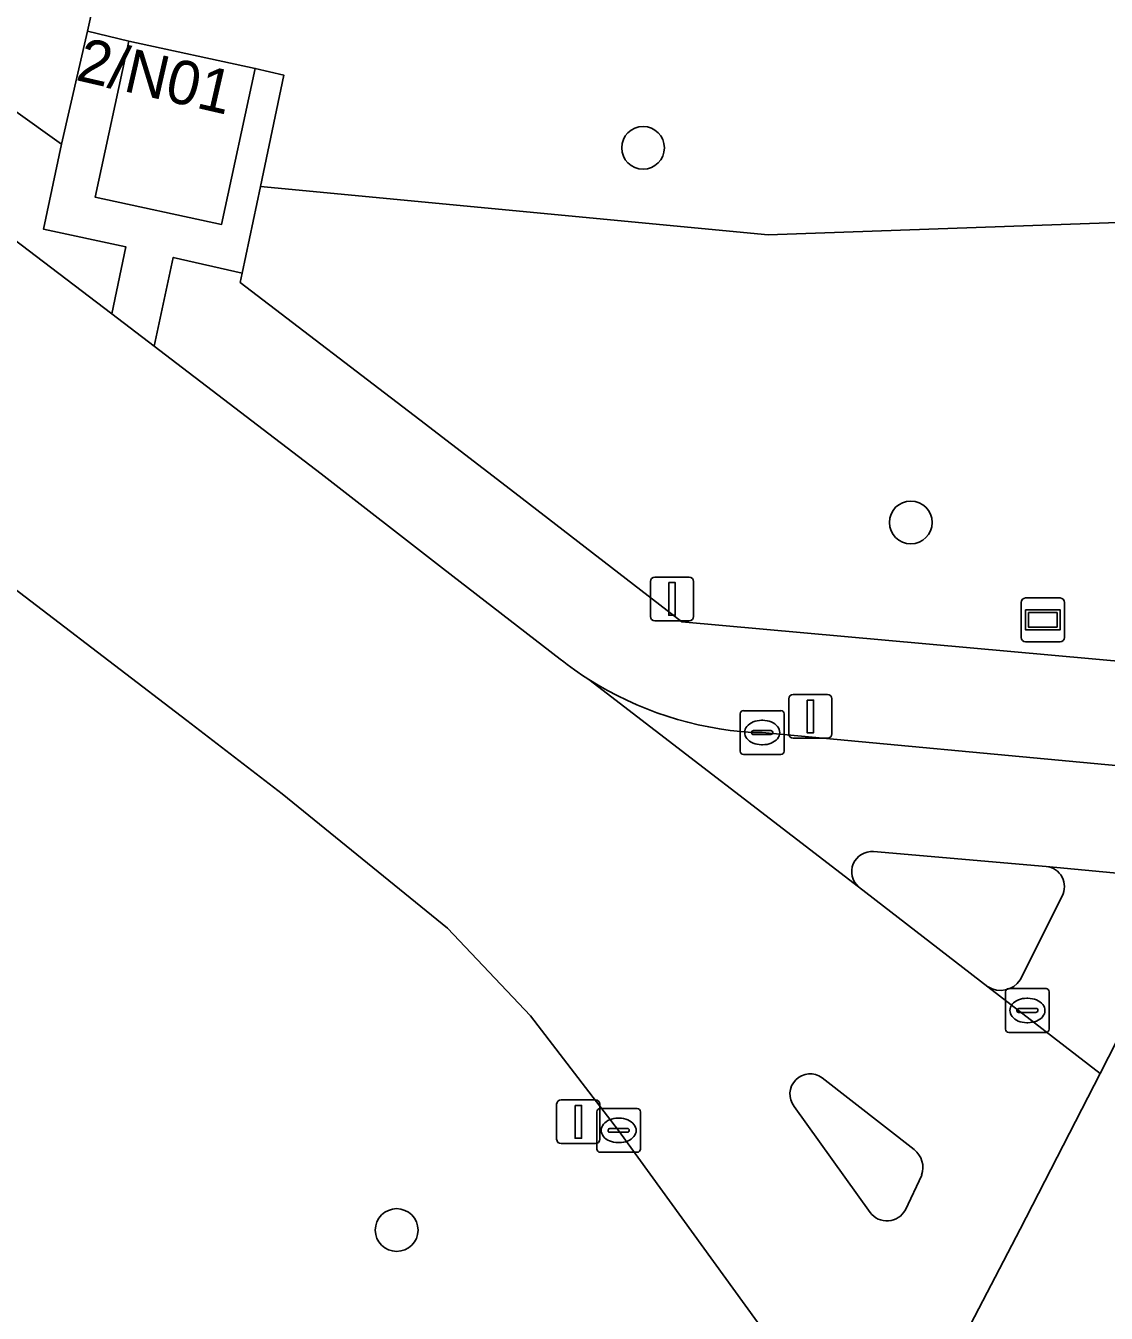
# Model space of a CAD drawing. Extents: x 161241 to 161758, y 384138 to 384885.
# Drawn here: x 161615.2 to 161639.93, y 384599.27 to 384628.73 of the extents above; entities that cross this region are included whole.
import ezdxf

# ---------------------------------------------------------------- set-up
doc = ezdxf.new("R2010")
doc.units = 0
for name, color, linetype in [('IMGEO_Boom', 7, 'Continuous'), ('IMGEO_Fietspad_gesloten', 7, 'Continuous'), ('IMGEO_Groenvoorziening', 7, 'Continuous'), ('IMGEO_Kolk', 7, 'Continuous'), ('IMGEO_Lichtmast', 7, 'Continuous'), ('IMGEO_Pand', 7, 'Continuous'), ('IMGEO_Pand_nummerreeks', 7, 'Continuous'), ('IMGEO_Reclamebord', 7, 'Continuous'), ('IMGEO_Rijbaan_lokaal_open', 7, 'Continuous'), ('IMGEO_Verkeersbordpaal', 7, 'Continuous'), ('IMGEO_Verkeerseiland_gesloten', 7, 'Continuous'), ('IMGEO_Voetpad_open', 7, 'Continuous')]:
    doc.layers.add(name, color=color, linetype=linetype)

msp = doc.modelspace()

# ---------------------------------------------------------------- linework, layer by layer
at = {"layer": 'IMGEO_Boom'}
for centre in [(161629.324, 384625.936), (161635.451, 384617.365), (161623.685, 384601.176)]:
    msp.add_circle(centre, 0.489, dxfattribs=at)
at = {"layer": 'IMGEO_Fietspad_gesloten'}
for points in [[(161628.086, 384613.771), (161634.257, 384609.025)], [(161640.22, 384611.795), (161632.051, 384612.558), (161631.812, 384612.558)], [(161634.6, 384609.834), (161638.553, 384609.494), (161642.039, 384609.166), (161639.785, 384604.754), (161637.958, 384601.195), (161636.626, 384598.646), (161633.723, 384592.905), (161631.945, 384589.377), (161625.518, 384576.727), (161628.195, 384575.423), (161628.393, 384575.761), (161629.79, 384578.533), (161632.228, 384576.565), (161632.384, 384576.488), (161633.956, 384579.527), (161633.252, 384580.024), (161631.645, 384581.275)]]:
    msp.add_lwpolyline(points, dxfattribs=at)
for centre, radius, start, end in [((161632.345, 384620.524), 7.984, 237.7617, 266.173), ((161634.563, 384609.373), 0.463, 85.3956, 228.6525)]:
    msp.add_arc(centre, radius, start, end, dxfattribs=at)
at = {"layer": 'IMGEO_Groenvoorziening'}
msp.add_lwpolyline([(161610.995, 384629.578), (161612.606, 384628.455), (161616.012, 384626.02), (161616.611, 384628.604), (161616.903, 384629.956), (161599.011, 384635.9)], dxfattribs=at)
for points in [[(161649.293, 384629.449), (161617.828, 384629.647), (161616.903, 384629.956), (161616.611, 384628.604), (161617.553, 384628.377), (161620.45, 384627.751), (161621.105, 384627.595), (161620.569, 384625.051), (161632.188, 384623.942), (161646.68, 384624.454), (161647.251, 384625.589)], [(161646.68, 384624.454), (161632.188, 384623.942), (161620.569, 384625.051), (161620.151, 384623.067), (161620.103, 384622.856), (161624.217, 384619.712), (161626.391, 384618.043), (161630.208, 384615.091), (161641.462, 384614.077)], [(161621.062, 384611.158), (161618.885, 384612.836), (161613.905, 384616.634), (161613.925, 384616.415), (161614.238, 384612.956), (161612.189, 384595.037), (161632.647, 384596.649), (161633.111, 384597.461), (161628.766, 384603.455), (161626.747, 384606.076), (161624.845, 384608.084)]]:
    msp.add_lwpolyline(points, close=True, dxfattribs=at)
at = {"layer": 'IMGEO_Kolk'}
for p, q in [((161631.625, 384613.058), (161632.477, 384613.058)), ((161631.55, 384612.132), (161631.55, 384612.984)), ((161632.038, 384612.838), (161632.063, 384612.838)), ((161632.551, 384612.984), (161632.551, 384612.132)), ((161631.809, 384612.552), (161631.809, 384612.564)), ((161632.247, 384612.515), (161631.849, 384612.515)), ((161631.852, 384612.601), (161632.25, 384612.601)), ((161632.293, 384612.564), (161632.293, 384612.552)), ((161632.061, 384612.278), (161632.036, 384612.278)), ((161632.477, 384612.058), (161631.625, 384612.058)), ((161637.62, 384605.773), (161637.62, 384606.625)), ((161637.695, 384606.699), (161638.547, 384606.699)), ((161638.621, 384606.625), (161638.621, 384605.773)), ((161637.922, 384606.242), (161638.32, 384606.242)), ((161638.108, 384606.479), (161638.133, 384606.479)), ((161637.879, 384606.193), (161637.879, 384606.205)), ((161638.317, 384606.156), (161637.919, 384606.156)), ((161638.363, 384606.205), (161638.363, 384606.193)), ((161638.547, 384605.699), (161637.695, 384605.699)), ((161638.131, 384605.919), (161638.106, 384605.919)), ((161628.265, 384603.029), (161628.265, 384603.881)), ((161628.34, 384603.955), (161629.192, 384603.955)), ((161629.266, 384603.881), (161629.266, 384603.029)), ((161628.753, 384603.735), (161628.778, 384603.735)), ((161628.524, 384603.449), (161628.524, 384603.461)), ((161628.962, 384603.412), (161628.564, 384603.412)), ((161628.567, 384603.498), (161628.965, 384603.498)), ((161629.008, 384603.461), (161629.008, 384603.449)), ((161628.776, 384603.175), (161628.751, 384603.175)), ((161629.192, 384602.955), (161628.34, 384602.955))]:
    msp.add_line(p, q, dxfattribs=at)
for points in [[(161631.625, 384613.058), (161632.477, 384613.058)], [(161631.55, 384612.132), (161631.55, 384612.984)], [(161632.551, 384612.984), (161632.551, 384612.132)], [(161632.477, 384612.058), (161631.625, 384612.058)], [(161637.62, 384605.773), (161637.62, 384606.625)], [(161637.695, 384606.699), (161638.547, 384606.699)], [(161638.621, 384606.625), (161638.621, 384605.773)], [(161638.547, 384605.699), (161637.695, 384605.699)], [(161628.265, 384603.029), (161628.265, 384603.881)], [(161628.34, 384603.955), (161629.192, 384603.955)], [(161629.266, 384603.881), (161629.266, 384603.029)], [(161629.192, 384602.955), (161628.34, 384602.955)]]:
    msp.add_lwpolyline(points, dxfattribs=at)
for centre, radius, start, end in [((161631.627, 384612.982), 0.0765, 91.552, 178.448), ((161631.627, 384612.982), 0.0765, 91.552, 178.448), ((161632.475, 384612.982), 0.0765, 1.552, 88.448), ((161632.475, 384612.982), 0.0765, 1.552, 88.448), ((161631.849, 384612.561), 0.0403, 85.8775, 175.7526), ((161631.846, 384612.551), 0.0366, 178.938, 274.7102), ((161632.25, 384612.558), 0.043, 264.8664, 352.4533), ((161632.254, 384612.563), 0.0386, 1.7309, 96.639), ((161631.627, 384612.134), 0.0765, 181.552, 268.448), ((161631.627, 384612.134), 0.0765, 181.552, 268.448), ((161632.475, 384612.134), 0.0765, 271.552, 358.448), ((161632.475, 384612.134), 0.0765, 271.552, 358.448), ((161637.697, 384606.623), 0.0765, 91.552, 178.448), ((161637.697, 384606.623), 0.0765, 91.552, 178.448), ((161638.545, 384606.623), 0.0765, 1.552, 88.448), ((161638.545, 384606.623), 0.0765, 1.552, 88.448), ((161637.919, 384606.202), 0.0403, 85.8775, 175.7526), ((161638.324, 384606.204), 0.0386, 1.7309, 96.639), ((161637.916, 384606.192), 0.0366, 178.938, 274.7102), ((161638.32, 384606.199), 0.043, 264.8664, 352.4533), ((161637.697, 384605.775), 0.0765, 181.552, 268.448), ((161637.697, 384605.775), 0.0765, 181.552, 268.448), ((161638.545, 384605.775), 0.0765, 271.552, 358.448), ((161638.545, 384605.775), 0.0765, 271.552, 358.448), ((161628.342, 384603.879), 0.0765, 91.552, 178.448), ((161628.342, 384603.879), 0.0765, 91.552, 178.448), ((161629.19, 384603.879), 0.0765, 1.552, 88.448), ((161629.19, 384603.879), 0.0765, 1.552, 88.448), ((161628.564, 384603.458), 0.0403, 85.8775, 175.7526), ((161628.561, 384603.448), 0.0366, 178.938, 274.7102), ((161628.965, 384603.455), 0.043, 264.8664, 352.4533), ((161628.969, 384603.46), 0.0386, 1.7309, 96.639), ((161628.342, 384603.031), 0.0765, 181.552, 268.448), ((161628.342, 384603.031), 0.0765, 181.552, 268.448), ((161629.19, 384603.031), 0.0765, 271.552, 358.448), ((161629.19, 384603.031), 0.0765, 271.552, 358.448)]:
    msp.add_arc(centre, radius, start, end, dxfattribs=at)
for centre, major_axis, ratio, start_param, end_param in [((161632.037, 384612.558), (-0.387, 0.002), 0.722429, 4.712389, 7.853982), ((161632.062, 384612.558), (-0.39, 0.002), 0.717154, 1.570796, 4.712389), ((161638.107, 384606.199), (-0.387, 0.002), 0.722429, 4.712389, 7.853982), ((161638.132, 384606.199), (-0.39, 0.002), 0.717154, 1.570796, 4.712389), ((161628.752, 384603.455), (-0.387, 0.002), 0.722429, 4.712389, 7.853982), ((161628.777, 384603.455), (-0.39, 0.002), 0.717154, 1.570796, 4.712389)]:
    msp.add_ellipse(centre, major_axis=major_axis, ratio=ratio, start_param=start_param, end_param=end_param, dxfattribs=at)
at = {"layer": 'IMGEO_Lichtmast'}
for p, q in [((161632.658, 384612.527), (161632.658, 384613.327)), ((161632.658, 384613.327), (161632.658, 384612.527)), ((161632.758, 384613.427), (161633.548, 384613.427)), ((161633.548, 384613.427), (161632.758, 384613.427)), ((161633.648, 384613.327), (161633.648, 384612.527)), ((161633.648, 384612.527), (161633.648, 384613.327)), ((161633.548, 384612.427), (161632.758, 384612.427)), ((161632.758, 384612.427), (161633.548, 384612.427)), ((161627.347, 384603.252), (161627.347, 384604.052)), ((161627.347, 384604.052), (161627.347, 384603.252)), ((161627.447, 384604.152), (161628.237, 384604.152)), ((161628.237, 384604.152), (161627.447, 384604.152)), ((161628.337, 384604.052), (161628.337, 384603.252)), ((161628.337, 384603.252), (161628.337, 384604.052)), ((161628.237, 384603.152), (161627.447, 384603.152)), ((161627.447, 384603.152), (161628.237, 384603.152))]:
    msp.add_line(p, q, dxfattribs=at)
for points in [[(161633.078, 384613.302), (161633.228, 384613.302), (161633.228, 384612.552), (161633.078, 384612.552), (161633.078, 384613.302)], [(161627.767, 384604.027), (161627.917, 384604.027), (161627.917, 384603.277), (161627.767, 384603.277), (161627.767, 384604.027)]]:
    msp.add_lwpolyline(points, dxfattribs=at)
for centre, start, end in [((161632.758, 384613.327), 90, 180), ((161632.758, 384613.327), 90, 180), ((161633.548, 384613.327), 0, 90), ((161633.548, 384613.327), 360, 90), ((161632.758, 384612.527), 180, 270), ((161632.758, 384612.527), 180, 270), ((161633.548, 384612.527), 270, 0), ((161633.548, 384612.527), 270, 0), ((161627.447, 384604.052), 90, 180), ((161627.447, 384604.052), 90, 180), ((161628.237, 384604.052), 0, 90), ((161628.237, 384604.052), 360, 90), ((161627.447, 384603.252), 180, 270), ((161627.447, 384603.252), 180, 270), ((161628.237, 384603.252), 270, 0), ((161628.237, 384603.252), 270, 0)]:
    msp.add_arc(centre, 0.1, start, end, dxfattribs=at)
at = {"layer": 'IMGEO_Pand'}
msp.add_lwpolyline([(161617.553, 384628.377), (161616.782, 384624.81), (161619.679, 384624.183), (161620.45, 384627.751)], close=True, dxfattribs=at)
at = {"layer": 'IMGEO_Reclamebord'}
for p, q in [((161637.978, 384614.736), (161637.978, 384615.536)), ((161637.978, 384615.536), (161637.978, 384614.736)), ((161638.078, 384615.636), (161638.868, 384615.636)), ((161638.868, 384615.636), (161638.078, 384615.636)), ((161638.968, 384615.536), (161638.968, 384614.736)), ((161638.968, 384614.736), (161638.968, 384615.536)), ((161638.868, 384614.636), (161638.078, 384614.636)), ((161638.078, 384614.636), (161638.868, 384614.636))]:
    msp.add_line(p, q, dxfattribs=at)
for points in [[(161638.079, 384615.368), (161638.867, 384615.368), (161638.867, 384614.904), (161638.079, 384614.904), (161638.079, 384615.368)], [(161638.144, 384615.303), (161638.144, 384614.969), (161638.802, 384614.969), (161638.802, 384615.303), (161638.144, 384615.303)]]:
    msp.add_lwpolyline(points, dxfattribs=at)
for centre, start, end in [((161638.078, 384615.536), 90, 180), ((161638.078, 384615.536), 90, 180), ((161638.868, 384615.536), 0, 90), ((161638.868, 384615.536), 360, 90), ((161638.078, 384614.736), 180, 270), ((161638.078, 384614.736), 180, 270), ((161638.868, 384614.736), 270, 0), ((161638.868, 384614.736), 270, 0)]:
    msp.add_arc(centre, 0.1, start, end, dxfattribs=at)
at = {"layer": 'IMGEO_Rijbaan_lokaal_open'}
for points in [[(161627.429, 384614.233), (161624.731, 384616.32), (161621.959, 384618.479), (161618.136, 384621.395), (161617.165, 384622.136), (161614.74, 384623.986), (161613.148, 384625.176), (161611.339, 384626.472)], [(161608.548, 384620.685), (161612.736, 384617.526), (161613.905, 384616.634), (161618.885, 384612.836), (161621.062, 384611.158), (161624.845, 384608.084), (161626.747, 384606.076), (161628.766, 384603.455), (161633.111, 384597.461), (161633.327, 384597.149)], [(161633.723, 384592.905), (161636.626, 384598.646), (161637.958, 384601.195), (161639.785, 384604.754), (161637.219, 384606.741), (161634.257, 384609.025), (161628.086, 384613.771)], [(161633.423, 384604.657), (161635.529, 384603.015)], [(161634.522, 384601.578), (161632.784, 384604.005)], [(161635.701, 384602.433), (161635.328, 384601.637)]]:
    msp.add_lwpolyline(points, dxfattribs=at)
for centre, radius, start, end in [((161632.533, 384620.793), 8.311, 232.1157, 237.6548), ((161633.146, 384604.289), 0.46, 53.0799, 218.0739), ((161635.204, 384602.603), 0.525, 341.1357, 51.7925), ((161634.906, 384601.862), 0.478, 216.4469, 331.9264)]:
    msp.add_arc(centre, radius, start, end, dxfattribs=at)
at = {"layer": 'IMGEO_Verkeersbordpaal'}
for p, q in [((161629.492, 384615.215), (161629.492, 384616.015)), ((161629.492, 384616.015), (161629.492, 384615.215)), ((161629.592, 384616.115), (161630.382, 384616.115)), ((161630.382, 384616.115), (161629.592, 384616.115)), ((161630.482, 384616.015), (161630.482, 384615.215)), ((161630.482, 384615.215), (161630.482, 384616.015)), ((161630.382, 384615.115), (161629.592, 384615.115)), ((161629.592, 384615.115), (161630.382, 384615.115))]:
    msp.add_line(p, q, dxfattribs=at)
msp.add_lwpolyline([(161629.912, 384615.99), (161630.062, 384615.99), (161630.062, 384615.24), (161629.912, 384615.24), (161629.912, 384615.99)], dxfattribs=at)
for centre, start, end in [((161629.592, 384616.015), 90, 180), ((161629.592, 384616.015), 90, 180), ((161630.382, 384616.015), 0, 90), ((161630.382, 384616.015), 360, 90), ((161629.592, 384615.215), 180, 270), ((161629.592, 384615.215), 180, 270), ((161630.382, 384615.215), 270, 0), ((161630.382, 384615.215), 270, 0)]:
    msp.add_arc(centre, 0.1, start, end, dxfattribs=at)
at = {"layer": 'IMGEO_Verkeerseiland_gesloten'}
for points in [[(161638.553, 384609.494), (161634.6, 384609.834)], [(161634.257, 384609.025), (161637.219, 384606.741)], [(161637.956, 384606.9), (161638.915, 384608.814)], [(161635.529, 384603.015), (161633.423, 384604.657)], [(161632.784, 384604.005), (161634.522, 384601.578)], [(161635.328, 384601.637), (161635.701, 384602.433)]]:
    msp.add_lwpolyline(points, dxfattribs=at)
for centre, radius, start, end in [((161634.563, 384609.373), 0.463, 85.3956, 228.6525), ((161638.505, 384609.032), 0.464, 331.9559, 84.1016), ((161637.508, 384607.189), 0.533, 237.2106, 327.1382), ((161633.146, 384604.289), 0.46, 53.0799, 218.0739), ((161635.204, 384602.603), 0.525, 341.1357, 51.7925), ((161634.906, 384601.862), 0.478, 216.4469, 331.9264)]:
    msp.add_arc(centre, radius, start, end, dxfattribs=at)
at = {"layer": 'IMGEO_Voetpad_open'}
for points in [[(161611.339, 384626.472), (161613.148, 384625.176), (161614.74, 384623.986), (161617.165, 384622.136), (161617.485, 384623.673), (161615.602, 384624.077), (161616.012, 384626.02), (161612.606, 384628.455), (161610.995, 384629.578)], [(161641.462, 384614.077), (161630.208, 384615.091), (161626.391, 384618.043), (161624.217, 384619.712), (161620.103, 384622.856), (161620.151, 384623.067), (161618.573, 384623.427), (161618.136, 384621.395), (161621.959, 384618.479), (161624.731, 384616.32), (161627.429, 384614.233)], [(161631.812, 384612.558), (161632.051, 384612.558), (161640.22, 384611.795), (161641.462, 384614.077)], [(161637.219, 384606.741), (161639.785, 384604.754), (161642.039, 384609.166), (161638.553, 384609.494)], [(161638.915, 384608.814), (161637.956, 384606.9)]]:
    msp.add_lwpolyline(points, dxfattribs=at)
msp.add_lwpolyline([(161620.569, 384625.051), (161621.105, 384627.595), (161620.45, 384627.751), (161619.679, 384624.183), (161616.782, 384624.81), (161617.553, 384628.377), (161616.611, 384628.604), (161616.012, 384626.02), (161615.602, 384624.077), (161617.485, 384623.673), (161617.165, 384622.136), (161618.136, 384621.395), (161618.573, 384623.427), (161620.151, 384623.067)], close=True, dxfattribs=at)
for centre, radius, start, end in [((161632.533, 384620.793), 8.311, 232.1157, 237.6548), ((161632.345, 384620.524), 7.984, 237.7617, 266.173), ((161638.505, 384609.032), 0.464, 331.9559, 84.1016), ((161637.508, 384607.189), 0.533, 237.2106, 327.1382)]:
    msp.add_arc(centre, radius, start, end, dxfattribs=at)

# ---------------------------------------------------------------- texts
at = {"layer": 'IMGEO_Pand_nummerreeks'}
msp.add_text('2/N01', height=1, rotation=347.0424, dxfattribs=at).set_placement((161616.315, 384627.491))

doc.saveas('drawing.dxf')
